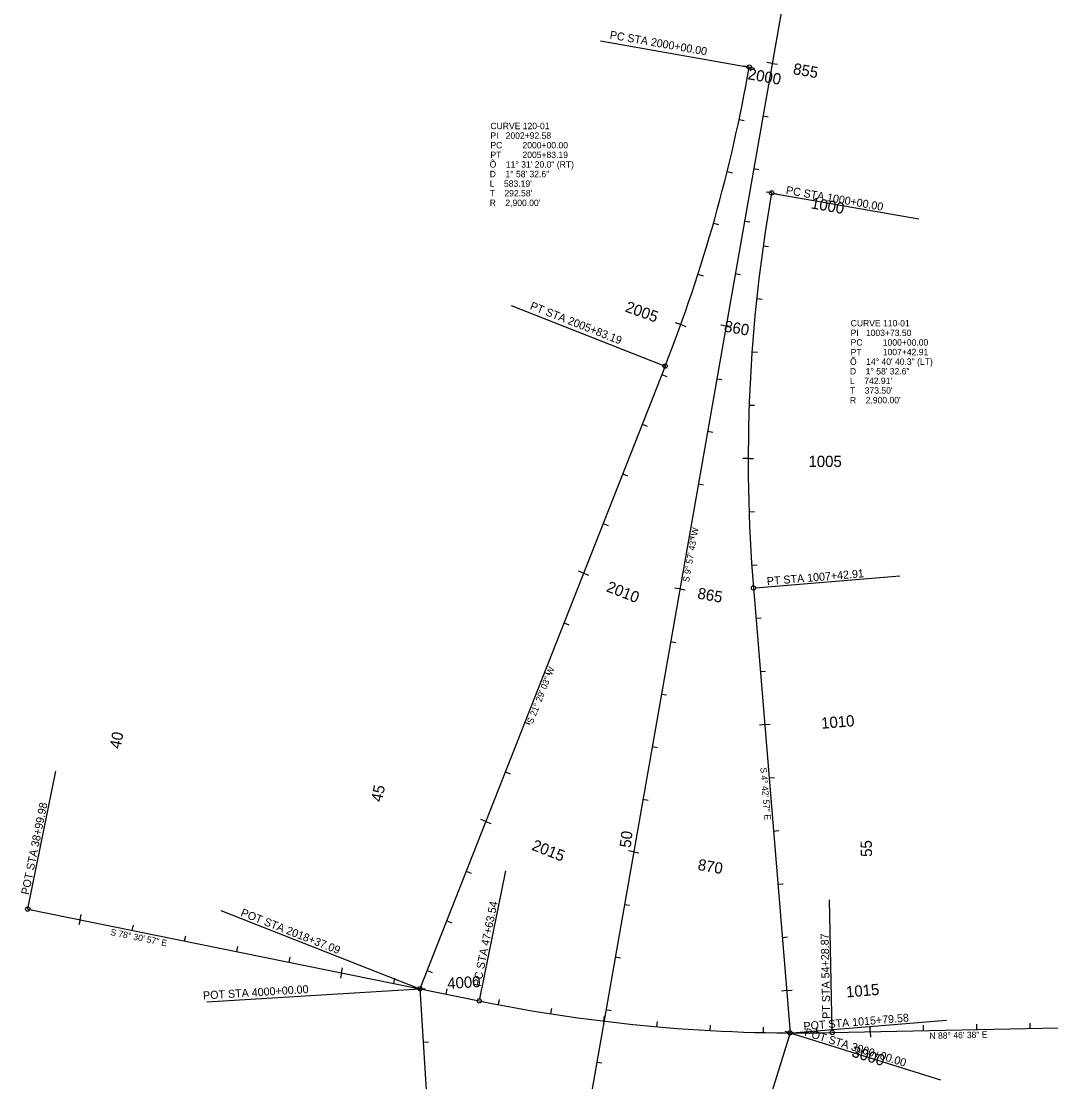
# Model space of a CAD drawing. Extents: x 2819977 to 2827606, y 113942 to 150283.
# Drawn here: x 2819977 to 2821906, y 132044 to 134032 of the extents above; entities that cross this region are included whole.
import ezdxf

# ---------------------------------------------------------------- set-up
doc = ezdxf.new("R2010")
doc.units = 0
for name, color, linetype in [('Level 63', 7, 'Continuous'), ('Roadway-Safety', 7, 'Continuous'), ('Roadway-Signs', 7, 'Continuous'), ('Roadway-Walls', 7, 'Continuous'), ('Utility-Power', 7, 'Continuous')]:
    doc.layers.add(name, color=color, linetype=linetype)

msp = doc.modelspace()

# ---------------------------------------------------------------- linework, layer by layer
at = {"layer": 'Level 63'}
for centre in [(2821340.6, 133945.8), (2821382.5, 133709.9), (2821182.9, 133385.4), (2821348.6, 132969.8), (2820723.6, 132218.6), (2821417.3, 132135.9)]:
    msp.add_circle(centre, 4, dxfattribs=at)
at = {"layer": 'Roadway-Safety'}
for p, q in [((2821062.2, 133994.7), (2821340.6, 133945.8)), ((2821386.4, 133709.2), (2821658.2, 133661.5)), ((2820894.5, 133498.9), (2821182.9, 133385.4)), ((2821352.5, 132970.1), (2821622.6, 132992.4)), ((2819989.5, 132371.8), (2820041.2, 132626.4)), ((2820835.7, 132199.9), (2820884.5, 132439.7)), ((2821496.1, 132140.6), (2821490.9, 132385.3)), ((2820350.5, 132365.4), (2820723.6, 132218.6)), ((2820324.5, 132194.1), (2820723.6, 132218.6)), ((2821421.3, 132136.3), (2821710.1, 132160.1)), ((2821421.2, 132134.8), (2821699, 132048.3))]:
    msp.add_line(p, q, dxfattribs=at)
at = {"layer": 'Utility-Power'}
for p, q in [((2821447.5, 134317.2), (2821007.1, 131809.7)), ((2821383.5, 133952.8), (2821373.7, 133954.5)), ((2821383.5, 133952.8), (2821393.3, 133951.1)), ((2821340.6, 133945.8), (2821330.8, 133947.5)), ((2821340.6, 133945.8), (2821350.5, 133944)), ((2821366.2, 133854.3), (2821376.1, 133852.6)), ((2821321.6, 133847.6), (2821331.4, 133845.5)), ((2821299.3, 133750.1), (2821309, 133747.7)), ((2821348.9, 133755.8), (2821358.8, 133754.1)), ((2821382.5, 133709.9), (2821372.6, 133711.6)), ((2821382.5, 133709.9), (2821392.3, 133708.2)), ((2821273.6, 133653.5), (2821283.2, 133650.8)), ((2821331.6, 133657.3), (2821341.5, 133655.6)), ((2821366.9, 133611.1), (2821376.8, 133609.7)), ((2821244.5, 133557.8), (2821254.1, 133554.8)), ((2821314.3, 133558.8), (2821324.2, 133557.1)), ((2821354.7, 133511.9), (2821364.6, 133510.8)), ((2821212.2, 133463.2), (2821202.8, 133466.6)), ((2821212.2, 133463.2), (2821221.6, 133459.8)), ((2821297, 133460.3), (2821287.2, 133462.1)), ((2821297, 133460.3), (2821306.9, 133458.6)), ((2821345.9, 133412.3), (2821355.9, 133411.5)), ((2821182.9, 133385.4), (2820723.6, 132218.6)), ((2821176.7, 133369.7), (2821186, 133366.1)), ((2821279.7, 133361.8), (2821289.6, 133360.1)), ((2821340.6, 133312.4), (2821350.6, 133312)), ((2821140.1, 133276.7), (2821149.4, 133273)), ((2821262.4, 133263.3), (2821272.3, 133261.6)), ((2821338.7, 133212.4), (2821328.7, 133212.4)), ((2821338.7, 133212.4), (2821348.7, 133212.4)), ((2821103.5, 133183.6), (2821112.8, 133179.9)), ((2821245.1, 133164.8), (2821255, 133163.1)), ((2821340.3, 133112.4), (2821350.3, 133112.8)), ((2821066.8, 133090.6), (2821076.1, 133086.9)), ((2821227.8, 133066.4), (2821237.7, 133064.6)), ((2821030.2, 132997.5), (2821020.9, 133001.2)), ((2821030.2, 132997.5), (2821039.5, 132993.8)), ((2821345.3, 133012.6), (2821355.3, 133013.2)), ((2821210.5, 132967.9), (2821200.7, 132969.6)), ((2821210.5, 132967.9), (2821220.4, 132966.1)), ((2821348.6, 132969.8), (2821417.3, 132135.9)), ((2820993.6, 132904.5), (2821002.9, 132900.8)), ((2821353.3, 132912.9), (2821363.2, 132913.7)), ((2821193.2, 132869.4), (2821203.1, 132867.6)), ((2820957, 132811.4), (2820966.3, 132807.7)), ((2821361.5, 132813.2), (2821371.4, 132814)), ((2821175.9, 132770.9), (2821185.8, 132769.2)), ((2820920.3, 132718.4), (2820929.6, 132714.7)), ((2821369.7, 132713.6), (2821359.7, 132712.7)), ((2821369.7, 132713.6), (2821379.7, 132714.4)), ((2821158.6, 132672.4), (2821168.5, 132670.7)), ((2820883.7, 132625.3), (2820893, 132621.6)), ((2821377.9, 132613.9), (2821387.9, 132614.7)), ((2821141.3, 132573.9), (2821151.2, 132572.2)), ((2820847.1, 132532.2), (2820837.8, 132535.9)), ((2820847.1, 132532.2), (2820856.4, 132528.6)), ((2821386.1, 132514.2), (2821396.1, 132515.1)), ((2821124, 132475.4), (2821114.2, 132477.1)), ((2821124, 132475.4), (2821133.9, 132473.7)), ((2820810.5, 132439.2), (2820819.8, 132435.5)), ((2821394.4, 132414.6), (2821404.3, 132415.4)), ((2819988.7, 132367.9), (2819990.7, 132377.7)), ((2819988.7, 132367.9), (2820834.9, 132196)), ((2821106.7, 132376.9), (2821116.6, 132375.2)), ((2820086.7, 132348), (2820084.7, 132338.2)), ((2820086.7, 132348), (2820088.7, 132357.8)), ((2820773.8, 132346.1), (2820783.2, 132342.5)), ((2820184.7, 132328.1), (2820186.7, 132337.9)), ((2820282.7, 132308.2), (2820284.7, 132318)), ((2821402.6, 132314.9), (2821412.5, 132315.7)), ((2820380.7, 132288.3), (2820382.7, 132298.1)), ((2821089.4, 132278.4), (2821099.3, 132276.7)), ((2820478.7, 132268.3), (2820480.7, 132278.1)), ((2820576.7, 132248.4), (2820574.7, 132238.6)), ((2820576.7, 132248.4), (2820578.7, 132258.2)), ((2820737.2, 132253.1), (2820746.5, 132249.4)), ((2820674.7, 132228.5), (2820676.7, 132238.3)), ((2820723.6, 132218.6), (2820733.6, 132219.2)), ((2820723.6, 132218.6), (2820713.7, 132218)), ((2820723.6, 132218.6), (2820799.5, 130984.2)), ((2820772.7, 132208.6), (2820774.7, 132218.4)), ((2821410.8, 132215.3), (2821400.8, 132214.4)), ((2821410.8, 132215.3), (2821420.8, 132216.1)), ((2820870.7, 132188.9), (2820872.6, 132198.7)), ((2820969.2, 132171.8), (2820970.8, 132181.7)), ((2821072.1, 132179.9), (2821082, 132178.2)), ((2821068.3, 132158.1), (2821069.5, 132168)), ((2821068.3, 132158.1), (2821067.1, 132148.1)), ((2821167.7, 132147.6), (2821168.6, 132157.5)), ((2821267.5, 132140.4), (2821268, 132150.4)), ((2821367.4, 132136.6), (2821367.6, 132146.6)), ((2821467.4, 132136.1), (2821467.3, 132146.1)), ((2821496.2, 132136.6), (2822062.3, 132148.7)), ((2821567.4, 132138.1), (2821567.1, 132148.1)), ((2821667.3, 132140.2), (2821667.1, 132150.2)), ((2821767.3, 132142.4), (2821767.1, 132152.4)), ((2821867.3, 132144.5), (2821867.1, 132154.5)), ((2821417.3, 132135.9), (2821006.7, 130816.2)), ((2821417.3, 132135.9), (2821407.8, 132138.9)), ((2821417.3, 132135.9), (2821426.9, 132133)), ((2821567.4, 132138.1), (2821567.6, 132128.1)), ((2820729.8, 132118.8), (2820739.7, 132119.4)), ((2821054.8, 132081.4), (2821064.7, 132079.7))]:
    msp.add_line(p, q, dxfattribs=at)
for centre in [(2819988.7, 132367.9), (2820723.6, 132218.6), (2820834.9, 132196), (2821417.3, 132135.9), (2821496.2, 132136.6)]:
    msp.add_circle(centre, 4, dxfattribs=at)
for centre, radius, start, end in [((2818484.4, 134447.5), 2900, 338.5158, 350.0381), ((2824238.7, 133208.2), 2900, 170.0381, 184.7159), ((2821432.2, 135135.9), 3000, 258.5158, 271.2227)]:
    msp.add_arc(centre, radius, start, end, dxfattribs=at)

# ---------------------------------------------------------------- texts
at = {"layer": 'Roadway-Safety'}
for s, rotation, p in [('PC STA 2000+00.00', 350.0381, (2821078.4, 133999.4)), ('PC STA 1000+00.00', 350.0381, (2821408.6, 133708.3)), ('PT STA 2005+83.19', 338.5158, (2820928.7, 133492.6)), ('PT STA 1007+42.91', 4.7159, (2821374.2, 132974.9)), ('POT STA 38+99.98', 78.5158, (2819990.9, 132394)), ('PC STA 47+63.54', 78.5158, (2820837.2, 132222)), ('POT STA 2018+37.09', 338.5158, (2820386.6, 132355.7)), ('PT STA 54+28.87', 91.2227, (2821492.7, 132162.5)), ('POT STA 4000+00.00', 3.5158, (2820317.7, 132198.6)), ('POT STA 1015+79.58', 4.7159, (2821443, 132141.1)), ('POT STA 3000+00.00', 342.7159, (2821443.1, 132131.1))]:
    msp.add_text(s, height=15, rotation=rotation, dxfattribs=at).set_placement(p)
at = {"layer": 'Roadway-Signs'}
for s, rotation, p in [('S 9%%d 57\' 43" W', 80.0381, (2821227.8, 132979.8)), ('S 21%%d 29\' 03" W', 68.5158, (2820934.9, 132714.3)), ('S 4%%d 42\' 57" E', 274.7159, (2821361.3, 132633.1)), ('S 78%%d 30\' 57" E', 348.5158, (2820142.8, 132319.5)), ('N 88%%d 46\' 38" E', 1.2227, (2821678.4, 132124.6))]:
    msp.add_text(s, height=12, rotation=rotation, dxfattribs=at).set_placement(p)
at = {"layer": 'Roadway-Walls'}
for s, p in [('CURVE 120-01', (2820855.7, 133829.4)), ('PI   2002+92.58', (2820855.7, 133811.4)), ('PC', (2820855.7, 133793.4)), ('2000+00.00', (2820915.8, 133793.4)), ('Õ    11%%d 31\' 20.0" (RT)', (2820854.3, 133757.4)), ('PT', (2820855.7, 133775.4)), ('2005+83.19', (2820915.8, 133775.4)), ('D    1%%d 58\' 32.6"', (2820854.3, 133739.4)), ("L    583.19'", (2820854.3, 133721.4)), ("T    292.58'", (2820854.3, 133703.4)), ("R    2,900.00'", (2820854.3, 133685.4)), ('CURVE 110-01', (2821530.7, 133459.8)), ('PI   1003+73.50', (2821530.7, 133441.8)), ('PC', (2821530.7, 133423.8)), ('1000+00.00', (2821590.9, 133423.8)), ('PT', (2821530.7, 133405.8)), ('1007+42.91', (2821590.9, 133405.8)), ('Õ    14%%d 40\' 40.3" (LT)', (2821529.4, 133387.8)), ('D    1%%d 58\' 32.6"', (2821529.4, 133369.8)), ("L    742.91'", (2821529.4, 133351.8)), ("T    373.50'", (2821529.4, 133333.8)), ("R    2,900.00'", (2821529.4, 133315.8))]:
    msp.add_text(s, height=12, dxfattribs=at).set_placement(p)
at = {"layer": 'Utility-Power'}
for s, rotation, p in [(' 855', 350.0381, (2821414, 133934.2)), (' 2000', 350.0381, (2821329.1, 133924.5)), (' 1000', 350.0381, (2821447.5, 133682.5)), (' 2005', 340.1595, (2821099.3, 133490.7)), (' 860', 350.0381, (2821284.7, 133451.8)), (' 1005', 359.9166, (2821443.8, 133196.5)), (' 2010', 338.5158, (2821064.1, 132966.7)), (' 865', 350.0381, (2821234.8, 132951.4)), (' 1010', 4.7159, (2821468.5, 132705.1)), (' 40', 78.5158, (2820160.7, 132659.5)), (' 45', 78.5158, (2820650.7, 132559.9)), (' 2015', 338.5158, (2820924.4, 132482.4)), (' 50', 83.0319, (2821117.5, 132474.4)), (' 55', 91.2227, (2821571, 132458.3)), (' 870', 350.0381, (2821235.3, 132442.9)), (' 4000', 3.5158, (2820767.6, 132217.7)), (' 1015', 4.7159, (2821515.1, 132201.6)), (' 3000', 342.7159, (2821523.5, 132094.4))]:
    msp.add_text(s, height=21, rotation=rotation, dxfattribs=at).set_placement(p)

doc.saveas('drawing.dxf')
